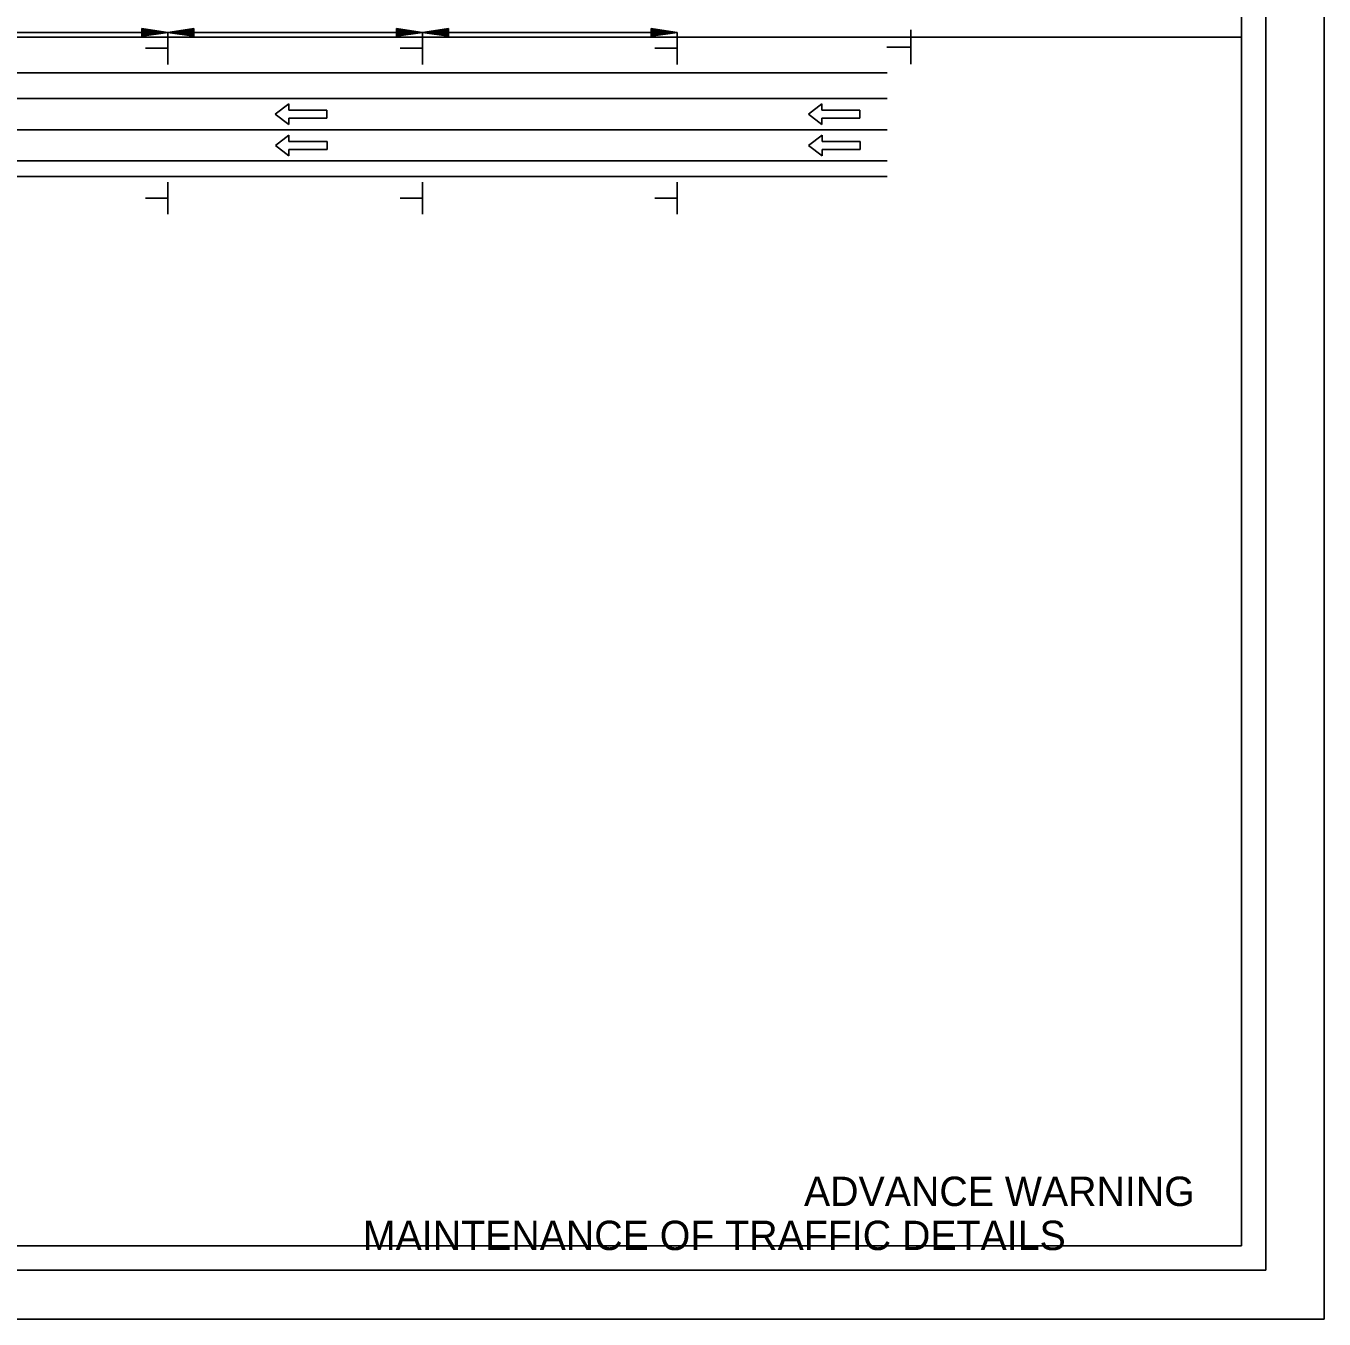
# Model space of a CAD drawing. Extents: x 13528 to 25043, y 7635 to 10612.
# Drawn here: x 14665 to 15195, y 9545 to 10073 of the extents above; entities that cross this region are included whole.
import ezdxf

# ---------------------------------------------------------------- set-up
doc = ezdxf.new("R2010")
doc.units = 0
for name, color, linetype in [('Default', 7, 'Continuous'), ('R_Border', 7, 'Continuous'), ('R_Border Plan-Plan', 7, 'Continuous'), ('R_Border Title', 7, 'Continuous'), ('R_Draft', 7, 'Continuous'), ('R_Revision Date Text', 7, 'Continuous')]:
    doc.layers.add(name, color=color, linetype=linetype)

msp = doc.modelspace()

# ---------------------------------------------------------------- linework, layer by layer
at = {"layer": 'Default'}
for p, q in [((14722.64, 10070.37), (14631.67, 10070.37)), ((14826.63, 10070.37), (14722.64, 10070.37)), ((14930.63, 10070.37), (14826.63, 10070.37)), ((15016.52, 10053.89), (14429.41, 10053.89)), ((15016.52, 10043.3), (14429.41, 10043.3)), ((14766.51, 10036.97), (14772.01, 10041.21)), ((14772.01, 10032.73), (14766.51, 10036.97)), ((14772.01, 10038.56), (14772.01, 10041.21)), ((14772.01, 10038.56), (14787.6, 10038.56)), ((14787.6, 10035.38), (14787.6, 10038.56)), ((14984.26, 10036.97), (14989.76, 10041.21)), ((14989.76, 10032.73), (14984.26, 10036.97)), ((14989.76, 10038.56), (14989.76, 10041.21)), ((14989.76, 10038.56), (15005.34, 10038.56)), ((15005.34, 10035.38), (15005.34, 10038.56)), ((14772.01, 10035.38), (14787.6, 10035.38)), ((14772.01, 10032.73), (14772.01, 10035.38)), ((14989.76, 10035.38), (15005.34, 10035.38)), ((14989.76, 10032.73), (14989.76, 10035.38)), ((15016.52, 10030.59), (14429.41, 10030.59)), ((14766.6, 10024.15), (14772.09, 10028.38)), ((14772.09, 10025.73), (14772.09, 10028.38)), ((14772.09, 10025.73), (14787.68, 10025.73)), ((14787.68, 10022.56), (14787.68, 10025.73)), ((14984.34, 10024.15), (14989.84, 10028.38)), ((14989.84, 10025.73), (14989.84, 10028.38)), ((14989.84, 10025.73), (15005.42, 10025.73)), ((15005.42, 10022.56), (15005.42, 10025.73)), ((14772.09, 10019.91), (14766.6, 10024.15)), ((14772.09, 10022.56), (14787.68, 10022.56)), ((14772.09, 10019.91), (14772.09, 10022.56)), ((14989.84, 10019.91), (14984.34, 10024.15)), ((14989.84, 10022.56), (15005.42, 10022.56)), ((14989.84, 10019.91), (14989.84, 10022.56)), ((15016.52, 10017.87), (14429.41, 10017.87)), ((15016.52, 10011.52), (14429.41, 10011.52))]:
    msp.add_line(p, q, dxfattribs=at)
at = {"layer": 'R_Border'}
for p, q in [((14722.64, 10070.37), (14722.64, 10057.28)), ((14826.63, 10070.37), (14826.63, 10057.28)), ((14930.63, 10070.37), (14930.63, 10057.28)), ((15026.11, 10071.36), (15026.18, 10057.34)), ((14722.44, 10063.86), (14713.51, 10063.86)), ((14826.44, 10063.86), (14817.51, 10063.86)), ((14930.44, 10063.86), (14921.51, 10063.86)), ((15026.15, 10064.38), (15016.37, 10064.34)), ((14722.64, 10009.19), (14722.64, 9996.1)), ((14826.63, 10009.19), (14826.63, 9996.1)), ((14930.63, 10009.19), (14930.63, 9996.1)), ((14722.44, 10002.67), (14713.51, 10002.67)), ((14826.44, 10002.67), (14817.51, 10002.67)), ((14930.44, 10002.67), (14921.51, 10002.67))]:
    msp.add_line(p, q, dxfattribs=at)
at = {"layer": 'R_Border Title'}
for p, q in [((14712.04, 10071.96), (14722.64, 10070.37)), ((14712.04, 10071.96), (14712.04, 10068.78)), ((14712.04, 10071.7), (14720.87, 10070.37)), ((14712.04, 10071.43), (14719.04, 10070.37)), ((14712.04, 10071.16), (14717.28, 10070.37)), ((14712.04, 10070.89), (14715.48, 10070.37)), ((14712.04, 10070.62), (14713.71, 10070.37)), ((14712.04, 10068.78), (14722.64, 10070.37)), ((14712.04, 10069.85), (14715.48, 10070.37)), ((14712.04, 10069.32), (14719.04, 10070.37)), ((14712.04, 10069.05), (14720.87, 10070.37)), ((14712.04, 10069.58), (14717.28, 10070.37)), ((14712.04, 10070.12), (14713.71, 10070.37)), ((14733.23, 10071.96), (14722.64, 10070.37)), ((14733.23, 10068.78), (14722.64, 10070.37)), ((14733.23, 10071.7), (14724.4, 10070.37)), ((14733.23, 10069.05), (14724.4, 10070.37)), ((14733.23, 10071.43), (14726.23, 10070.37)), ((14733.23, 10069.32), (14726.23, 10070.37)), ((14733.23, 10071.16), (14727.99, 10070.37)), ((14733.23, 10069.58), (14727.99, 10070.37)), ((14733.23, 10070.89), (14729.79, 10070.37)), ((14733.23, 10069.86), (14729.79, 10070.37)), ((14733.23, 10070.62), (14731.56, 10070.37)), ((14733.23, 10070.12), (14731.56, 10070.37)), ((14733.23, 10068.78), (14733.23, 10071.96)), ((14816.04, 10071.96), (14826.63, 10070.37)), ((14816.04, 10071.96), (14816.04, 10068.78)), ((14816.04, 10071.7), (14824.86, 10070.37)), ((14816.04, 10071.43), (14823.04, 10070.37)), ((14816.04, 10071.16), (14821.28, 10070.37)), ((14816.04, 10070.89), (14819.48, 10070.37)), ((14816.04, 10070.62), (14817.71, 10070.37)), ((14816.04, 10068.78), (14826.63, 10070.37)), ((14816.04, 10069.85), (14819.48, 10070.37)), ((14816.04, 10069.32), (14823.04, 10070.37)), ((14816.04, 10069.05), (14824.86, 10070.37)), ((14816.04, 10069.58), (14821.28, 10070.37)), ((14816.04, 10070.12), (14817.71, 10070.37)), ((14837.23, 10071.96), (14826.63, 10070.37)), ((14837.23, 10068.78), (14826.63, 10070.37)), ((14837.23, 10071.7), (14828.4, 10070.37)), ((14837.23, 10069.05), (14828.4, 10070.37)), ((14837.23, 10071.43), (14830.22, 10070.37)), ((14837.23, 10069.32), (14830.22, 10070.37)), ((14837.23, 10071.16), (14831.99, 10070.37)), ((14837.23, 10069.58), (14831.99, 10070.37)), ((14837.23, 10070.89), (14833.78, 10070.37)), ((14837.23, 10069.86), (14833.78, 10070.37)), ((14837.23, 10070.62), (14835.55, 10070.37)), ((14837.23, 10070.12), (14835.55, 10070.37)), ((14837.23, 10068.78), (14837.23, 10071.96)), ((14920.04, 10071.96), (14930.63, 10070.37)), ((14920.04, 10071.96), (14920.04, 10068.78)), ((14920.04, 10071.7), (14928.86, 10070.37)), ((14920.04, 10071.43), (14927.04, 10070.37)), ((14920.04, 10071.16), (14925.28, 10070.37)), ((14920.04, 10070.89), (14923.48, 10070.37)), ((14920.04, 10070.62), (14921.71, 10070.37)), ((14920.04, 10068.78), (14930.63, 10070.37)), ((14920.04, 10069.85), (14923.48, 10070.37)), ((14920.04, 10069.32), (14927.04, 10070.37)), ((14920.04, 10069.05), (14928.86, 10070.37)), ((14920.04, 10069.58), (14925.28, 10070.37)), ((14920.04, 10070.12), (14921.71, 10070.37))]:
    msp.add_line(p, q, dxfattribs=at)
at = {"layer": 'R_Draft'}
for q in [(15171.12, 10592.07), (13590.22, 9564.77)]:
    msp.add_line((15171.12, 9564.77), q, dxfattribs=at)
at = {"layer": 'R_Revision Date Text'}
for points in [[(13528.19, 10611.55), (15194.89, 10611.55), (15194.89, 9544.86), (13528.19, 9544.86)], [(13600.22, 10582.07), (14847.92, 10582.07), (14847.92, 10532.67), (14935.62, 10532.67), (15056.12, 10532.67), (15056.12, 10421.01), (15161.12, 10421.01), (15161.12, 9574.77), (13600.22, 9574.77)], [(13600.22, 10068.42), (15161.12, 10068.42), (15161.12, 9574.77), (13600.22, 9574.77)]]:
    msp.add_lwpolyline(points, close=True, dxfattribs=at)

# ---------------------------------------------------------------- texts
at = {"layer": 'R_Border Plan-Plan'}
for s, p in [('ADVANCE WARNING', (14982.48, 9591.02)), ('MAINTENANCE OF TRAFFIC DETAILS', (14802.32, 9573.02))]:
    msp.add_text(s, height=12, dxfattribs=at).set_placement(p)

doc.saveas('drawing.dxf')
